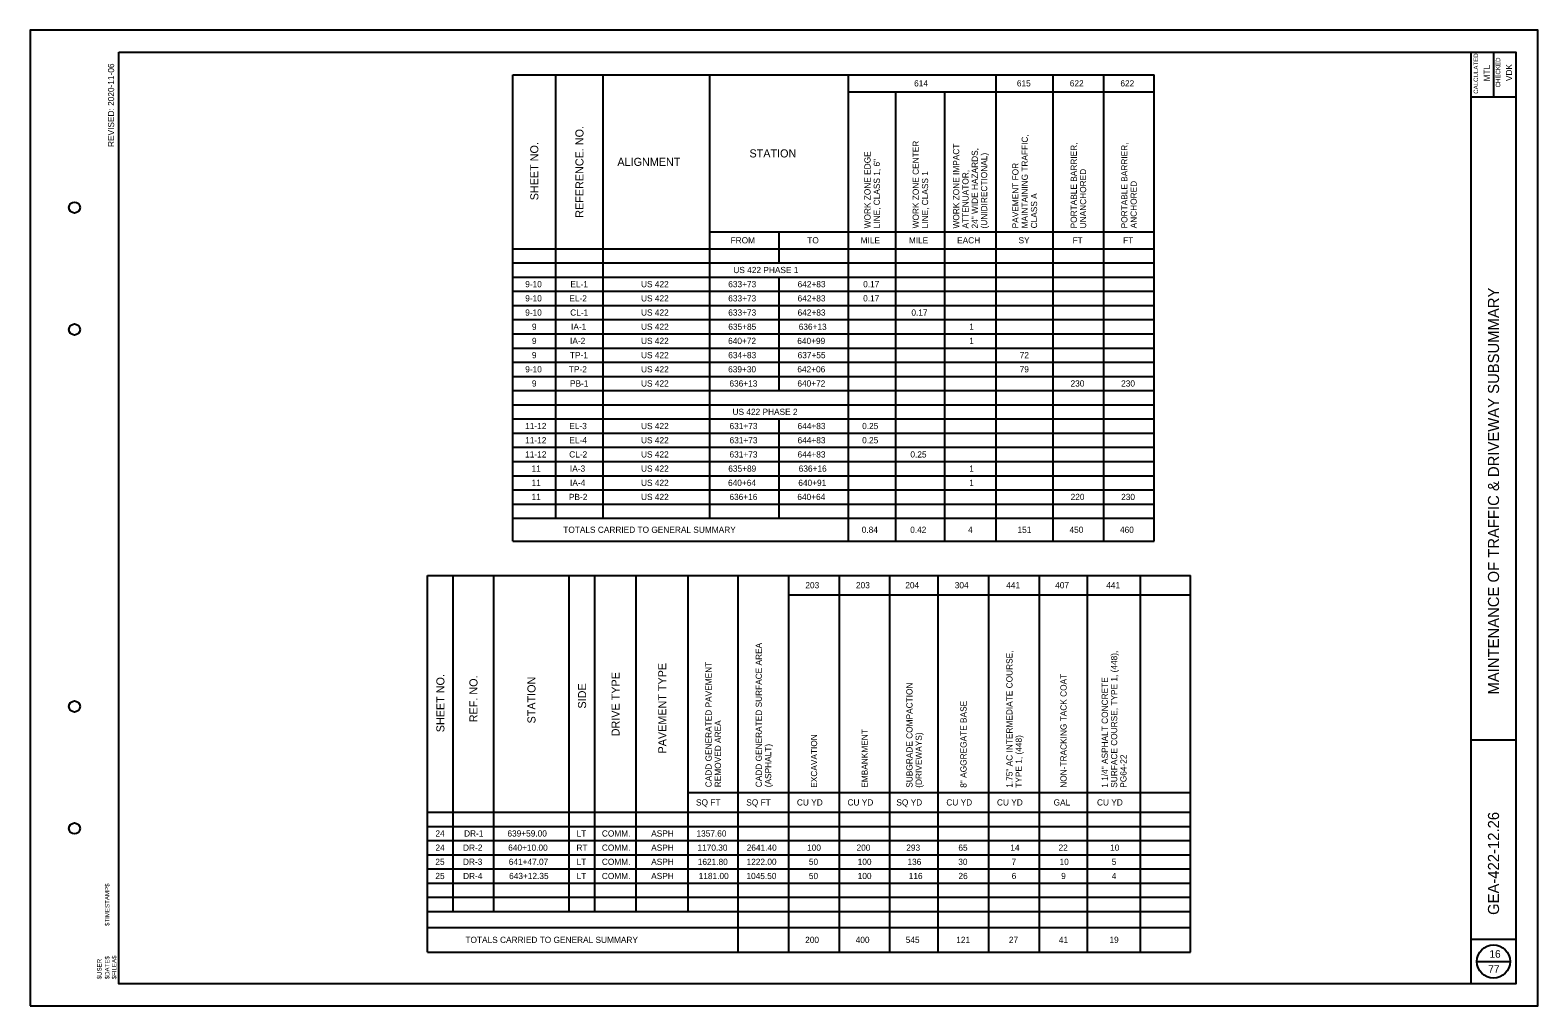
# Model space of a CAD drawing. Extents: x 0 to 34, y 0 to 22.
import ezdxf

# ---------------------------------------------------------------- set-up
doc = ezdxf.new("R2010")
doc.units = 0
for name, color, linetype in [('SH_Border', 7, 'Continuous'), ('SH_Cut_Line', 7, 'Continuous'), ('SH_Data', 7, 'Continuous'), ('SH_Text', 7, 'Continuous')]:
    doc.layers.add(name, color=color, linetype=linetype)

msp = doc.modelspace()

# ---------------------------------------------------------------- linework, layer by layer
at = {"layer": 'SH_Border'}
for p, q in [((32.5, 0.5), (32.5, 21.5)), ((33, 21.5), (33, 20.5)), ((32.5, 20.5), (33.5, 20.5)), ((32.5, 6), (33.5, 6)), ((32.5, 1.5), (33.5, 1.5))]:
    msp.add_line(p, q, dxfattribs=at)
msp.add_lwpolyline([(2, 21.5), (33.5, 21.5), (33.5, 0.5), (2, 0.5)], close=True, dxfattribs=at)
for centre in [(1, 18), (1, 15.25), (1, 6.75), (1, 4)]:
    msp.add_circle(centre, 0.125, dxfattribs=at)
at = {"layer": 'SH_Cut_Line'}
msp.add_lwpolyline([(0, 0), (34, 0), (34, 22), (0, 22)], close=True, dxfattribs=at)
at = {"layer": 'SH_Data'}
msp.add_line((32.625, 1), (33.375, 1), dxfattribs=at)
msp.add_circle((33, 1), 0.375, dxfattribs=at)
at = {"layer": 'SH_Text'}
for p, q in [((10.886, 20.991), (10.886, 20.991)), ((10.886, 20.991), (25.35, 20.991)), ((10.886, 10.475), (10.886, 20.991)), ((11.851, 10.995), (11.851, 20.991)), ((12.922, 10.995), (12.922, 20.991)), ((15.327, 10.995), (15.327, 20.991)), ((18.452, 10.475), (18.452, 20.991)), ((21.787, 10.475), (21.787, 20.991)), ((23.068, 10.475), (23.068, 20.991)), ((24.209, 10.475), (24.209, 20.991)), ((25.35, 10.475), (25.35, 20.991)), ((18.452, 20.611), (25.35, 20.611)), ((19.522, 10.475), (19.522, 20.611)), ((20.628, 10.475), (20.628, 20.611)), ((15.327, 17.452), (25.35, 17.452)), ((16.889, 16.752), (16.889, 17.452)), ((10.886, 17.072), (25.35, 17.072)), ((10.886, 16.752), (25.35, 16.752)), ((10.886, 16.433), (25.35, 16.433)), ((16.889, 13.874), (16.889, 16.433)), ((10.886, 16.113), (25.35, 16.113)), ((10.886, 15.793), (25.35, 15.793)), ((10.886, 15.473), (25.35, 15.473)), ((10.886, 15.153), (25.35, 15.153)), ((10.886, 14.833), (25.35, 14.833)), ((10.886, 14.513), (25.35, 14.513)), ((10.886, 14.193), (25.35, 14.193)), ((10.886, 13.874), (25.35, 13.874)), ((10.886, 13.554), (25.35, 13.554)), ((10.886, 13.234), (25.35, 13.234)), ((16.889, 10.995), (16.889, 13.234)), ((10.886, 12.914), (25.35, 12.914)), ((10.886, 12.594), (25.35, 12.594)), ((10.886, 12.274), (25.35, 12.274)), ((10.886, 11.954), (25.35, 11.954)), ((10.886, 11.634), (25.35, 11.634)), ((10.886, 11.315), (25.35, 11.315)), ((10.886, 10.995), (25.35, 10.995)), ((10.886, 10.475), (25.35, 10.475)), ((8.962, 9.705), (8.962, 9.705)), ((8.962, 9.705), (26.164, 9.705)), ((8.962, 1.208), (8.962, 9.705)), ((9.541, 2.128), (9.541, 9.705)), ((10.454, 2.128), (10.454, 9.705)), ((12.157, 2.128), (12.157, 9.705)), ((12.736, 2.128), (12.736, 9.705)), ((13.666, 2.128), (13.666, 9.705)), ((14.842, 2.128), (14.842, 9.705)), ((15.966, 1.208), (15.966, 9.705)), ((17.107, 1.208), (17.107, 9.705)), ((18.248, 1.208), (18.248, 9.705)), ((19.389, 1.208), (19.389, 9.705)), ((20.477, 1.208), (20.477, 9.705)), ((21.618, 1.208), (21.618, 9.705)), ((22.759, 1.208), (22.759, 9.705)), ((23.847, 1.208), (23.847, 9.705)), ((25.041, 1.208), (25.041, 9.705)), ((26.164, 1.208), (26.164, 9.705)), ((17.107, 9.265), (26.164, 9.265)), ((14.842, 4.807), (26.164, 4.807)), ((8.962, 4.367), (26.164, 4.367)), ((8.962, 4.047), (26.164, 4.047)), ((8.962, 3.727), (26.164, 3.727)), ((8.962, 3.407), (26.164, 3.407)), ((8.962, 3.088), (26.164, 3.088)), ((8.962, 2.768), (26.164, 2.768)), ((8.962, 2.448), (26.164, 2.448)), ((8.962, 2.128), (26.164, 2.128)), ((8.962, 1.768), (26.164, 1.768)), ((8.962, 1.208), (26.164, 1.208))]:
    msp.add_line(p, q, dxfattribs=at)

# ---------------------------------------------------------------- texts
at = {"layer": 'SH_Data'}
for s, height, rotation, p in [('CALCULATED', 0.1, 90, (32.652, 20.565)), ('MTL', 0.14, 90, (32.92, 20.844)), ('CHECKED', 0.1, 90, (33.152, 20.708)), ('VDK', 0.14, 90, (33.42, 20.851)), ('MAINTENANCE OF TRAFFIC & DRIVEWAY SUBSUMMARY', 0.25, 90, (33.125, 7.02)), (' GEA-422-12.26 ', 0.25, 90, (33.125, 1.957)), ('$TIMESTAMP$', 0.1, 89.9931, (1.788, 1.8)), ('$USER', 0.1, 89.9931, (1.611, 0.598)), ('$DATE$', 0.1, 89.9931, (1.788, 0.598)), ('$FILEA$', 0.1, 89.9931, (1.944, 0.598))]:
    msp.add_text(s, height=height, rotation=rotation, dxfattribs=at).set_placement(p)
for s, p in [('16', (32.908, 1.085)), ('77', (32.882, 0.745))]:
    msp.add_text(s, height=0.17, dxfattribs=at).set_placement(p)
at = {"layer": 'SH_Text'}
for s, height, p in [('REVISED: 2020-11-06', 0.14, (1.894, 19.366)), ('REFERENCE. NO.', 0.182, (12.478, 17.77)), ('SHEET NO.', 0.182, (11.46, 18.164)), ('WORK ZONE CENTER', 0.14, (20.04, 17.531)), ('WORK ZONE IMPACT', 0.14, (20.952, 17.528)), ('MAINTAINING TRAFFIC,', 0.14, (22.498, 17.531)), ('PORTABLE BARRIER,', 0.14, (23.604, 17.531)), ('PORTABLE BARRIER,', 0.14, (24.745, 17.531)), ('WORK ZONE EDGE', 0.14, (18.952, 17.531)), ('LINE, CLASS 1, 6"', 0.14, (19.162, 17.531)), ('24" WIDE HAZARDS,', 0.14, (21.372, 17.528)), ('(UNIDIRECTIONAL)', 0.14, (21.582, 17.528)), ('LINE, CLASS 1', 0.14, (20.25, 17.531)), ('ATTENUATOR,', 0.14, (21.162, 17.528)), ('PAVEMENT FOR', 0.14, (22.288, 17.531)), ('UNANCHORED', 0.14, (23.814, 17.531)), ('ANCHORED', 0.14, (24.955, 17.531)), ('CLASS A', 0.14, (22.708, 17.531)), ('CADD GENERATED SURFACE AREA', 0.14, (16.501, 4.929)), ('1.75" AC INTERMEDIATE COURSE,', 0.14, (22.153, 4.918)), ('SURFACE COURSE, TYPE 1, (448),', 0.14, (24.514, 4.918)), ('DRIVE TYPE', 0.182, (13.292, 6.078)), ('PAVEMENT TYPE', 0.182, (14.345, 5.69)), ('CADD GENERATED PAVEMENT', 0.14, (15.369, 4.929)), ('NON-TRACKING TACK COAT', 0.14, (23.373, 4.918)), ('SHEET NO.', 0.182, (9.342, 6.169)), ('REF. NO.', 0.182, (10.088, 6.395)), ('STATION', 0.182, (11.396, 6.368)), ('SIDE', 0.182, (12.537, 6.704)), ('SUBGRADE COMPACTION', 0.14, (19.898, 4.918)), ('1 1/4" ASPHALT CONCRETE', 0.14, (24.304, 4.918)), ('8" AGGREGATE BASE', 0.14, (21.117, 4.918)), ('REMOVED AREA', 0.14, (15.579, 4.929)), ('EMBANKMENT', 0.14, (18.888, 4.918)), ('(DRIVEWAYS) ', 0.14, (20.108, 4.918)), ('(ASPHALT)', 0.14, (16.711, 4.929)), ('EXCAVATION', 0.14, (17.747, 4.918)), ('TYPE 1, (448)', 0.14, (22.363, 4.918)), ('PG64-22', 0.14, (24.724, 4.918))]:
    msp.add_text(s, height=height, rotation=90, dxfattribs=at).set_placement(p)
for s, height, p in [('614', 0.14, (19.934, 20.731)), ('615', 0.14, (22.252, 20.731)), ('622', 0.14, (23.445, 20.731)), ('622', 0.14, (24.586, 20.731)), ('ALIGNMENT', 0.182, (13.243, 18.94)), ('STATION', 0.182, (16.222, 19.13)), ('FROM', 0.14, (15.796, 17.192)), ('TO', 0.14, (17.525, 17.192)), ('MILE', 0.14, (18.728, 17.192)), ('MILE', 0.14, (19.816, 17.192)), ('EACH', 0.14, (20.904, 17.192)), ('SY', 0.14, (22.288, 17.192)), ('FT', 0.14, (23.507, 17.192)), ('FT', 0.14, (24.648, 17.192)), ('US 422 PHASE 1', 0.14, (15.858, 16.522)), ('9-10', 0.14, (11.164, 16.203)), ('EL-1', 0.14, (12.183, 16.203)), ('US 422', 0.14, (13.776, 16.203)), ('633+73', 0.14, (15.743, 16.203)), ('642+83', 0.14, (17.307, 16.203)), ('0.17', 0.14, (18.785, 16.203)), ('9-10', 0.14, (11.164, 15.883)), ('EL-2', 0.14, (12.16, 15.883)), ('US 422', 0.14, (13.776, 15.883)), ('633+73', 0.14, (15.743, 15.883)), ('642+83', 0.14, (17.307, 15.883)), ('0.17', 0.14, (18.785, 15.883)), ('9-10', 0.14, (11.164, 15.563)), ('CL-1', 0.14, (12.179, 15.563)), ('US 422', 0.14, (13.776, 15.563)), ('633+73', 0.14, (15.743, 15.563)), ('642+83', 0.14, (17.307, 15.563)), ('0.17', 0.14, (19.873, 15.563)), ('9', 0.14, (11.316, 15.243)), ('IA-1', 0.14, (12.198, 15.243)), ('US 422', 0.14, (13.776, 15.243)), ('635+85', 0.14, (15.744, 15.243)), ('636+13', 0.14, (17.332, 15.243)), ('1', 0.14, (21.178, 15.243)), ('9', 0.14, (11.316, 14.923)), ('IA-2', 0.14, (12.175, 14.923)), ('US 422', 0.14, (13.776, 14.923)), ('640+72', 0.14, (15.74, 14.923)), ('640+99', 0.14, (17.3, 14.923)), ('1', 0.14, (21.178, 14.923)), ('9', 0.14, (11.316, 14.603)), ('TP-1', 0.14, (12.173, 14.603)), ('US 422', 0.14, (13.776, 14.603)), ('634+83', 0.14, (15.743, 14.603)), ('637+55', 0.14, (17.307, 14.603)), ('72', 0.14, (22.316, 14.603)), ('9-10', 0.14, (11.164, 14.283)), ('TP-2', 0.14, (12.149, 14.283)), ('US 422', 0.14, (13.776, 14.283)), ('639+30', 0.14, (15.74, 14.283)), ('642+06', 0.14, (17.301, 14.283)), ('79', 0.14, (22.315, 14.283)), ('9', 0.14, (11.316, 13.964)), ('PB-1', 0.14, (12.174, 13.964)), ('US 422', 0.14, (13.776, 13.964)), ('636+13', 0.14, (15.77, 13.964)), ('640+72', 0.14, (17.302, 13.964)), ('230', 0.14, (23.462, 13.964)), ('230', 0.14, (24.603, 13.964)), ('US 422 PHASE 2', 0.14, (15.839, 13.324)), ('11-12', 0.14, (11.163, 13.004)), ('EL-3', 0.14, (12.158, 13.004)), ('US 422', 0.14, (13.776, 13.004)), ('631+73', 0.14, (15.772, 13.004)), ('644+83', 0.14, (17.306, 13.004)), ('0.25', 0.14, (18.762, 13.004)), ('11-12', 0.14, (11.163, 12.684)), ('EL-4', 0.14, (12.16, 12.684)), ('US 422', 0.14, (13.776, 12.684)), ('631+73', 0.14, (15.772, 12.684)), ('644+83', 0.14, (17.306, 12.684)), ('0.25', 0.14, (18.762, 12.684)), ('11-12', 0.14, (11.163, 12.364)), ('CL-2', 0.14, (12.156, 12.364)), ('US 422', 0.14, (13.776, 12.364)), ('631+73', 0.14, (15.772, 12.364)), ('644+83', 0.14, (17.306, 12.364)), ('0.25', 0.14, (19.85, 12.364)), ('11', 0.14, (11.307, 12.044)), ('IA-3', 0.14, (12.173, 12.044)), ('US 422', 0.14, (13.776, 12.044)), ('635+89', 0.14, (15.744, 12.044)), ('636+16', 0.14, (17.332, 12.044)), ('1', 0.14, (21.178, 12.044)), ('11', 0.14, (11.307, 11.724)), ('IA-4', 0.14, (12.175, 11.724)), ('US 422', 0.14, (13.776, 11.724)), ('640+64', 0.14, (15.738, 11.724)), ('640+91', 0.14, (17.323, 11.724)), ('1', 0.14, (21.178, 11.724)), ('11', 0.14, (11.307, 11.405)), ('PB-2', 0.14, (12.15, 11.405)), ('US 422', 0.14, (13.776, 11.405)), ('636+16', 0.14, (15.77, 11.405)), ('640+64', 0.14, (17.301, 11.405)), ('220', 0.14, (23.464, 11.405)), ('230', 0.14, (24.603, 11.405)), ('TOTALS CARRIED TO GENERAL SUMMARY', 0.14, (12.022, 10.665)), ('0.84', 0.14, (18.753, 10.665)), ('0.42', 0.14, (19.846, 10.665)), ('4', 0.14, (21.151, 10.665)), ('151', 0.14, (22.266, 10.665)), ('450', 0.14, (23.438, 10.665)), ('460', 0.14, (24.577, 10.665)), ('203', 0.14, (17.482, 9.415)), ('203', 0.14, (18.623, 9.415)), ('204', 0.14, (19.736, 9.415)), ('304', 0.14, (20.851, 9.415)), ('441', 0.14, (22.012, 9.415)), ('407', 0.14, (23.115, 9.415)), ('441', 0.14, (24.268, 9.415)), ('SQ FT', 0.14, (15.016, 4.517)), ('SQ FT', 0.14, (16.149, 4.517)), ('CU YD', 0.14, (17.291, 4.517)), ('CU YD', 0.14, (18.432, 4.517)), ('SQ YD', 0.14, (19.534, 4.517)), ('CU YD', 0.14, (20.661, 4.517)), ('CU YD', 0.14, (21.802, 4.517)), ('GAL', 0.14, (23.08, 4.517)), ('CU YD', 0.14, (24.058, 4.517)), ('24', 0.14, (9.14, 3.817)), ('DR-1', 0.14, (9.785, 3.817)), ('639+59.00', 0.14, (10.763, 3.817)), ('LT', 0.14, (12.324, 3.817)), ('COMM.', 0.14, (12.893, 3.817)), ('ASPH', 0.14, (14.005, 3.817)), ('1357.60', 0.14, (15.026, 3.817)), ('24', 0.14, (9.14, 3.497)), ('DR-2', 0.14, (9.762, 3.497)), ('640+10.00', 0.14, (10.781, 3.497)), ('RT', 0.14, (12.32, 3.497)), ('COMM.', 0.14, (12.893, 3.497)), ('ASPH', 0.14, (14.005, 3.497)), ('1170.30', 0.14, (15.049, 3.497)), ('2641.40', 0.14, (16.159, 3.497)), ('100', 0.14, (17.521, 3.497)), ('200', 0.14, (18.636, 3.497)), ('293', 0.14, (19.758, 3.497)), ('65', 0.14, (20.932, 3.497)), ('14', 0.14, (22.104, 3.497)), ('22', 0.14, (23.191, 3.497)), ('10', 0.14, (24.355, 3.497)), ('25', 0.14, (9.138, 3.178)), ('DR-3', 0.14, (9.76, 3.178)), ('641+47.07', 0.14, (10.793, 3.178)), ('LT', 0.14, (12.324, 3.178)), ('COMM.', 0.14, (12.893, 3.178)), ('ASPH', 0.14, (14.005, 3.178)), ('1621.80', 0.14, (15.055, 3.178)), ('1222.00', 0.14, (16.156, 3.178)), ('50', 0.14, (17.561, 3.178)), ('100', 0.14, (18.662, 3.178)), ('136', 0.14, (19.784, 3.178)), ('30', 0.14, (20.93, 3.178)), ('7', 0.14, (22.132, 3.178)), ('10', 0.14, (23.214, 3.178)), ('5', 0.14, (24.391, 3.178)), ('25', 0.14, (9.138, 2.858)), ('DR-4', 0.14, (9.763, 2.858)), ('643+12.35', 0.14, (10.801, 2.858)), ('LT', 0.14, (12.324, 2.858)), ('COMM.', 0.14, (12.893, 2.858)), ('ASPH', 0.14, (14.005, 2.858)), ('1181.00', 0.14, (15.076, 2.858)), ('1045.50', 0.14, (16.153, 2.858)), ('50', 0.14, (17.561, 2.858)), ('100', 0.14, (18.662, 2.858)), ('116', 0.14, (19.813, 2.858)), ('26', 0.14, (20.934, 2.858)), ('6', 0.14, (22.134, 2.858)), ('9', 0.14, (23.25, 2.858)), ('4', 0.14, (24.392, 2.858)), ('TOTALS CARRIED TO GENERAL SUMMARY', 0.14, (9.816, 1.418)), ('200', 0.14, (17.477, 1.418)), ('400', 0.14, (18.617, 1.418)), ('545', 0.14, (19.745, 1.418)), ('121', 0.14, (20.885, 1.418)), ('27', 0.14, (22.072, 1.418)), ('41', 0.14, (23.198, 1.418)), ('19', 0.14, (24.339, 1.418))]:
    msp.add_text(s, height=height, dxfattribs=at).set_placement(p)

doc.saveas('drawing.dxf')
